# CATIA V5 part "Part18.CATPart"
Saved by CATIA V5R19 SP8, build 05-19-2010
Part number: Entretoise_b
Bounding box of the stored display mesh (mm): x -51.986 to 51.986, y -51.986 to 51.986, z 122.494 to 187.494
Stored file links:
  G:\EU_thinkMotion\CFAO_2010\MMS_groupe1\MMS_groupe1\OK\ppiault\piault\piault_cfao\Part18.CATPart
  D:\Catia\Finaltest.CATProduct
  G:\Catia Projet\CFAO2\Product2.CATProduct
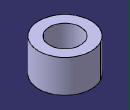
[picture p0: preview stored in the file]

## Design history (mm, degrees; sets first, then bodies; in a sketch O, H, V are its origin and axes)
External parameters (linked from other documents)
  External.LongueurEntretoise = 130 mm
Body1 (main body)
  Sketch1 on yz-plane, origin (0, 0, 0), H (0, 1, 0), V (0, 0, 1)
    line L1 (-31, 187.4938) -> (-31, 122.4938)
    line L2 (-52, 187.4938) -> (-31, 187.4938)
    line L3 (-52, 122.4938) -> (-52, 187.4938)
    line L4 (-31, 122.4938) -> (-52, 122.4938)
    length L2 = 21
    length L1 = 65 {= External.LongueurEntretoise /2}
    distance V L3 = 52
    distance L1 V = 31
    vertical: L1 V, L3 V
  Shaft1: profile Sketch1, axis Sketch1.V, angle 360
